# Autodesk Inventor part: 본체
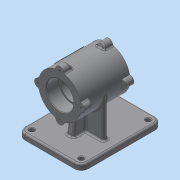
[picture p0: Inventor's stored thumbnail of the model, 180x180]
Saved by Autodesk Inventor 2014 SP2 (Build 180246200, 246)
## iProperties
Created: 2015-12
Part Number: 본체
Material: 일반
Document SubType Name: Modeling
Designer: 201-19
Density: 1 g/cm^3
Appearance: 기본값
Author: 201-19
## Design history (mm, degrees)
sketch "스케치1"
  geometry: C1 r 37 at (0, 0); 1 further point
  constraints: 1 centre point, 1 coincident
  dimensions: "d0" = 74 diameter of C1
extrude "돌출1" new body sketch "스케치1" stored distance "d1" = 85; taper "d2" = 0 deg
node "작업 평면1"
sketch "스케치4"
  geometry: L1 (-55, -70)-(55, -70); L2 (55, -70)-(55, -80); L3 (55, -80)-(-55, -80); L4 (-55, -80)-(-55, -70); C1 r 37 at (0, 0) reference; 2 further points
  constraints: 8 end point, 2 parallel, 1 horizontal, 1 midpoint, 1 perpendicular, 1 vertical alignment
  dimensions: "d7" = 110 distance of L2.end L3.end; "d8" = 10 distance of L1.end L2.end; "d9" = 80 distance from line of L3 point (0, 0)
extrude "돌출2" join sketch "스케치4" distance "d10" = 60; taper "d11" = 0 deg; dims "d12" = 80, "d13" = 0
node "작업 평면2"
sketch "스케치5"
  geometry: L1 (55, -70)-(55, -80) reference; L2 (55, -80)-(-55, -80) reference; L3 (-55, -80)-(-55, -70) reference; L4 (-55, -70)-(55, -70) reference; L5 (-37, 0)-(-37, -70); L6 (37, 0)-(37, -70); A1 r 37 centre (0, 0) between (-37, 0) and (37, 0) reference; 1 further point
  constraints: 4 end point, 2 perpendicular, 2 point on circle, 2 point on line
  dimensions: "d14" = 74 distance between parallel lines of L6 L5
extrude "돌출3" join sketch "스케치5" stored distance "d15" = 8; taper "d16" = 0 deg
sketch "스케치6"
  geometry: L1 (37, -42.5)-(-37, -42.5) reference; L2 (-37, -42.5)-(-37, -4) reference; L3 (-37, -4)-(-70, -4) reference; L4 (-70, -4)-(-70, -80) reference; L5 (-70, -80)-(-80, -80) reference; L6 (-80, -80)-(-80, 60) reference; L7 (-80, 60)-(-70, 60) reference; L8 (-70, 60)-(-70, 4) reference; L9 (-70, 4)-(-37, 4) reference; L10 (-37, 4)-(-37, 42.5) reference; L11 (-37, 42.5)-(37, 42.5) reference; L12 (37, 42.5)-(37, -42.5) reference; L13 (-70, 25)-(-37, 20.948); 1 further point
  constraints: 2 end point, 2 point on line
  dimensions: "d17" = 97 deg angle of L8 L13; "d18" = 25 vertical distance of point (0, 0) L13.start
feature "리브1" sketch "스케치6" dims "d19" = 1, "d20" = 12, "d21" = 0, "d22" = 0, "d23" = 1, "d24" = 1
node "작업 평면3"
fillet "모깎기1" dims "d25" = 12
hole "구멍1" diameter "d28" = 8; stored, may be unused: countersink angle "d32" = 90 deg, drill point angle "d34" = 118 deg; dims "d26" = 10, "d27" = 10, "d29" = 6, "d30" = 4, "d31" = 2, "d33" = 8
chamfer "모따기1" distance "d35" = 1; stored, may be unused: second distance "d36" = 2, angle "d37" = 45 deg
node "작업 평면5"
  node "작업 평면4"
sketch "스케치9"
  geometry: L1 (-85, 0)-(0, 0) reference; L2 (-85, 37)-(-85, -37) reference; 3 further points
  constraints: 1 coincident, 1 midpoint, 1 other
  dimensions: "d55" = 42.5 distance from line of point (-42.5, 0) L2
feature "엠보싱1" sketch "스케치9" dims "d56" = 0.5, "d57" = 0
fillet "모깎기2" dims "d58" = 3
fillet "모깎기3" dims "d59" = 3
fillet "모깎기4" dims "d60" = 3
fillet "모깎기5" dims "d61" = 3
fillet "모깎기6" dims "d62" = 3
sketch "스케치10"
  geometry: C1 r 37 at (0, 0) reference; C2 r 21 at (0, 0)
  constraints: 1 centre point, 1 coincident
  dimensions: "d63" = 42 diameter of C2
extrude "돌출5" cut sketch "스케치10" stored distance "d64" = 15; taper "d65" = 0 deg
sketch "스케치11"
  geometry: C1 r 21 at (0, 0) reference; C2 r 37 at (0, 0) reference; C3 r 23.5 at (0, 0)
  constraints: 1 centre point, 1 coincident
  dimensions: "d66" = 47 diameter of C3
extrude "돌출6" cut sketch "스케치11" distance "d67" = 22; taper "d68" = 0 deg
sketch "스케치12"
  geometry: C1 r 21 at (0, 0) reference; C2 r 23.5 at (0, 0)
  constraints: 1 centre point, 1 coincident
  dimensions: "d69" = 47 diameter of C2
extrude "돌출7" cut sketch "스케치12" distance "d70" = 22; taper "d71" = 0 deg
chamfer "모따기2" distance "d72" = 1; stored, may be unused: second distance "d73" = 2, angle "d74" = 45 deg
fillet "모깎기7" dims "d75" = 0.3
revolve "회전2" stored, may be unused: angle "d90" = 90 deg
sketch "스케치19"
  geometry: L1 (23.5, 20.8)-(23.5, 41.5) reference; L2 (23.5, 41.5)-(24.5, 42.5) reference; L3 (24.5, 42.5)-(44, 42.5) reference; L4 (44, 42.5)-(44, 30.048) reference; L5 (44, 30.048)-(37, 30.048) reference; L6 (37, 30.048)-(37, -42.5) reference; L7 (37, -42.5)-(24.5, -42.5) reference; L8 (24.5, -42.5)-(23.5, -41.5) reference; L9 (23.5, -41.5)-(23.5, -20.8) reference; L10 (23.2, -20.5)-(21, -20.5) reference; L11 (21, -20.5)-(21, 20.5) reference; L12 (21, 20.5)-(23.2, 20.5) reference; L13 (-70, 57)-(-70, 27.654) reference; L14 (-67.366, 24.677)-(-40.366, 21.361) reference; L15 (-37, 24.339)-(-37, 42.5) reference; L16 (-37, 42.5)-(-24.5, 42.5) reference; L17 (-24.5, 42.5)-(-23.5, 41.5) reference; L18 (-23.5, 41.5)-(-23.5, 20.8) reference; L19 (-23.2, 20.5)-(-21, 20.5) reference; L20 (-21, 20.5)-(-21, -20.5) reference; L21 (-21, -20.5)-(-23.2, -20.5) reference; L22 (-23.5, -20.8)-(-23.5, -41.5) reference; L23 (-23.5, -41.5)-(-24.5, -42.5) reference; L24 (-24.5, -42.5)-(-37, -42.5) reference; L25 (-37, -42.5)-(-37, -24.339) reference; L26 (-40.366, -21.361)-(-67.366, -24.677) reference; L27 (-70, -27.654)-(-70, -77) reference; L28 (-73, -80)-(-80, -80) reference; L29 (-80, -80)-(-80, 60) reference; L30 (-80, 60)-(-73, 60) reference; L31 (44, 30.048)-(31.634, 25.547); L32 (44, 30.048)-(31.634, 30.048); L33 (31.634, 30.048)-(31.634, 25.547); A1 r 0.3 centre (23.2, 20.8) between (23.2, 20.5) and (23.5, 20.8) reference; A2 r 0.3 centre (23.2, -20.8) between (23.5, -20.8) and (23.2, -20.5) reference; A3 r 3 centre (-73, 57) between (-70, 57) and (-73, 60) reference; A4 r 3 centre (-67, 27.654) between (-70, 27.654) and (-67.366, 24.677) reference; A5 r 0.3 centre (-23.2, 20.8) between (-23.5, 20.8) and (-23.2, 20.5) reference; A6 r 0.3 centre (-23.2, -20.8) between (-23.2, -20.5) and (-23.5, -20.8) reference; A7 r 3 centre (-67, -27.654) between (-67.366, -24.677) and (-70, -27.654) reference; A8 r 3 centre (-73, -77) between (-73, -80) and (-70, -77) reference; 1 further point
  constraints: 6 end point, 1 parallel, 1 perpendicular, 1 vertical alignment, 2 other
  dimensions: "d91" = 110 deg angle of L6 L31; "d92" = 12.36636 distance of L4.end L32.end
extrude "돌출10" join sketch "스케치19" stored distance "d93" = 14; taper "d94" = 0 deg
sketch "스케치20"
  geometry: L1 (7, 0)-(0, 0) reference; L2 (0, -7)-(0, 0) reference; L3 (0, 0)-(0, -7.668) reference; L4 (7, 0)-(0, 0) reference; L5 (14, 0)-(7, 0) reference; L6 (14, -7.668)-(14, 0) reference; A1 r 7 centre (7, -7) between (7, 0) and (0, -7) reference; A2 r 37 centre (7, -44) between (14, -7.668) and (0, -7.668) reference; 1 further point
extrude "돌출11" cut sketch "스케치20" stored distance "d95" = 14; taper "d96" = 0 deg
sketch "스케치21"
  geometry: L1 (7, 0)-(7, -7) reference; L2 (7, 0)-(0, 0) reference; A1 r 7 centre (0, -7) between (7, -7) and (0, 0) reference; 1 further point
extrude "돌출12" cut sketch "스케치21" stored distance "d97" = 14; taper "d98" = 0 deg
hole "구멍2" diameter "d102" = 3.242; stored, may be unused: countersink angle "d106" = 90 deg, drill point angle "d108" = 118 deg; dims "d100" = 10, "d101" = 10, "d103" = 9, "d104" = 4, "d105" = 2, "d107" = 11
revolve "회전3" stored, may be unused: angle "d118" = 90 deg
sketch "스케치18"
  geometry: L1 (23.5, 20.8)-(23.5, 41.5) reference; L2 (23.5, 41.5)-(24.5, 42.5) reference; L3 (24.5, 42.5)-(37, 42.5) reference; L4 (37, 42.5)-(37, -42.5) reference; L5 (37, -42.5)-(24.5, -42.5) reference; L6 (24.5, -42.5)-(23.5, -41.5) reference; L7 (23.5, -41.5)-(23.5, -20.8) reference; L8 (23.2, -20.5)-(21, -20.5) reference; L9 (21, -20.5)-(21, 20.5) reference; L10 (21, 20.5)-(23.2, 20.5) reference; L11 (-37, 24.339)-(-37, 42.5) reference; L12 (-37, 42.5)-(-24.5, 42.5) reference; L13 (-24.5, 42.5)-(-23.5, 41.5) reference; L14 (-23.5, 41.5)-(-23.5, 20.8) reference; L15 (-23.2, 20.5)-(-21, 20.5) reference; L16 (-21, 20.5)-(-21, -20.5) reference; L17 (-21, -20.5)-(-23.2, -20.5) reference; L18 (-23.5, -20.8)-(-23.5, -41.5) reference; L19 (-23.5, -41.5)-(-24.5, -42.5) reference; L20 (-24.5, -42.5)-(-37, -42.5) reference; L21 (-37, -42.5)-(-37, -24.339) reference; L22 (-40.366, -21.361)-(-67.366, -24.677) reference; L23 (-70, -27.654)-(-70, -77) reference; L24 (-73, -80)-(-80, -80) reference; L25 (-80, -80)-(-80, 60) reference; L26 (-80, 60)-(-73, 60) reference; L27 (-70, 57)-(-70, 27.654) reference; L28 (-67.366, 24.677)-(-40.366, 21.361) reference; L29 (37, 42.5)-(44, 42.5); L30 (44, 42.5)-(44, 30.048); L31 (44, 30.048)-(37, 27.5); L32 (44, 30.048)-(37, 30.048); L33 (0, 0)-(91.194, 0); L34 (0, 0)-(0, -85.079); L35 (0, 0)-(0, 76.409); L36 (44, -42.5)-(44, -30.048); L37 (37, -42.5)-(44, -42.5); L38 (44, -30.048)-(37, -30.048); L39 (44, -30.048)-(37, -27.5); L40 (-44, -42.5)-(-44, -30.048); L41 (-44, -30.048)-(-37, -30.048); L42 (-44, -30.048)-(-37, -27.5); L43 (-37, -42.5)-(-44, -42.5); L44 (-44, 42.5)-(-44, 30.048); L45 (-37, 42.5)-(-44, 42.5); L46 (-44, 30.048)-(-37, 27.5); L47 (-44, 30.048)-(-37, 30.048); L48 (37, -42.5)-(37, -30.048); L49 (-37, -42)-(-37, -30.048); L50 (-37, 42.5)-(-37, 30.048); L51 (37, -30.048)-(35.446, -30.048); L52 (35.446, -30.048)-(35.446, -26.934); L53 (35.446, -26.934)-(37, -27.5); A1 r 0.3 centre (23.2, 20.8) between (23.2, 20.5) and (23.5, 20.8) reference; A2 r 0.3 centre (23.2, -20.8) between (23.5, -20.8) and (23.2, -20.5) reference; A3 r 0.3 centre (-23.2, 20.8) between (-23.5, 20.8) and (-23.2, 20.5) reference; A4 r 0.3 centre (-23.2, -20.8) between (-23.2, -20.5) and (-23.5, -20.8) reference; A5 r 3 centre (-67, -27.654) between (-67.366, -24.677) and (-70, -27.654) reference; A6 r 3 centre (-73, -77) between (-73, -80) and (-70, -77) reference; A7 r 3 centre (-73, 57) between (-70, 57) and (-73, 60) reference; A8 r 3 centre (-67, 27.654) between (-70, 27.654) and (-67.366, 24.677) reference
  constraints: 50 end point, 12 symmetric about line, 5 perpendicular, 4 collinear, 3 point on line, 2 parallel, 1 vertical, 2 other
  dimensions: "d87" = 110 deg angle of L4 L31; "d88" = 7 distance of L3.end L29.end; "d89" = 15 vertical distance of L31.end L29.end; "d122" = 3.11332 distance of L51.end L52.end
extrude "돌출13" join sketch "스케치18" stored distance "d123" = 14; taper "d124" = 0 deg
sketch "스케치22"
  geometry: L1 (0, 0)-(7, 0) reference; L2 (0, -7)-(0, 0) reference; A1 r 7 centre (7, -7) between (7, 0) and (0, -7) reference; 1 further point
node "작업 평면8"
sketch "스케치23"
  geometry: L1 (0, 0)-(7, 0) reference; L2 (0, -7)-(0, 0) reference; A1 r 7 centre (7, -7) between (7, 0) and (0, -7) reference; 1 further point
extrude "돌출14" cut sketch "스케치22" stored distance "d128" = 14; taper "d129" = 0 deg
sketch "스케치24"
  geometry: L1 (7, 0)-(7, -7) reference; L2 (0, 0)-(7, 0) reference; A1 r 7 centre (0, -7) between (7, -7) and (0, 0) reference; 1 further point
extrude "돌출15" cut sketch "스케치24" stored distance "d130" = 14; taper "d131" = 0 deg
sketch "스케치25"
  geometry: L1 (0, 0)-(7, 0) reference; L2 (0, -7)-(0, 0) reference; L3 (0, -14)-(0, -7) reference; L4 (7, -14)-(0, -14) reference; A1 r 7 centre (7, -7) between (7, 0) and (0, -7) reference; A2 r 7 centre (7, -7) between (0, -7) and (7, -14) reference; 1 further point
extrude "돌출16" cut sketch "스케치25" stored distance "d132" = 14; taper "d133" = 0 deg
sketch "스케치26"
  geometry: L1 (0, 0)-(0, 7) reference; L2 (7, 0)-(0, 0) reference; L3 (14, 0)-(7, 0) reference; L4 (14, 7)-(14, 0) reference; A1 r 7 centre (7, 7) between (0, 7) and (7, 0) reference; A2 r 7 centre (7, 7) between (7, 0) and (14, 7) reference; 1 further point
extrude "돌출17" cut sketch "스케치26" stored distance "d134" = 14; taper "d135" = 0 deg
sketch "스케치27"
  geometry: L1 (7, 0)-(7, -7) reference; L2 (0, 0)-(7, 0) reference; L3 (7, -14)-(0, -14) reference; L4 (7, -7)-(7, -14) reference; A1 r 7 centre (0, -7) between (7, -7) and (0, 0) reference; A2 r 7 centre (0, -7) between (0, -14) and (7, -7) reference; 1 further point
extrude "돌출18" cut sketch "스케치27" stored distance "d136" = 14; taper "d137" = 0 deg
sketch "스케치28"
  geometry: L1 (0, 7)-(0, 0) reference; L2 (0, 0)-(7, 0) reference; L3 (14, 0)-(14, 7) reference; L4 (7, 0)-(14, 0) reference; L5 (14, 0)-(14, 7) reference; A1 r 7 centre (7, 7) between (0, 7) and (7, 0) reference; A2 r 7 centre (7, 7) between (7, 0) and (14, 7) reference; 1 further point
extrude "돌출19" cut sketch "스케치28" stored distance "d138" = 0; taper "d139" = 0 deg
fillet "모깎기11" dims "d140" = 3
fillet "모깎기12" dims "d141" = 3
fillet "모깎기13" dims "d142" = 3
hole "구멍3" diameter "d145" = 3.242; stored, may be unused: countersink angle "d149" = 90 deg, drill point angle "d151" = 118 deg; dims "d143" = 10, "d144" = 10, "d146" = 9, "d147" = 4, "d148" = 2, "d150" = 11
node "작업 평면9"
node "솔리드1"
mirror "대칭1"
pattern_linear "직사각형 패턴1" dims "d40" = 86
pattern_linear "직사각형 패턴2" dims "d43" = 116
pattern_circular "원형 패턴3" dims angle "d120" = 360 deg
pattern_circular "원형 패턴4" dims angle "d126" = 360 deg
mirror "대칭4"
pattern_circular "원형 패턴5" dims angle "d153" = 360 deg
mirror "대칭5"
node "작업축1"
node "투영된 루프1"
node "투영된 루프2"
node "투영된 루프3"
node "투영된 루프4"
node "투영된 루프5"
node "절단 모서리 투영2"
node "절단 모서리 투영3"
node "절단 모서리 투영5"
node "절단 모서리 투영8"
node "절단 모서리 투영9"
other parameters: "d53" = 45 deg, "d54" = 37
